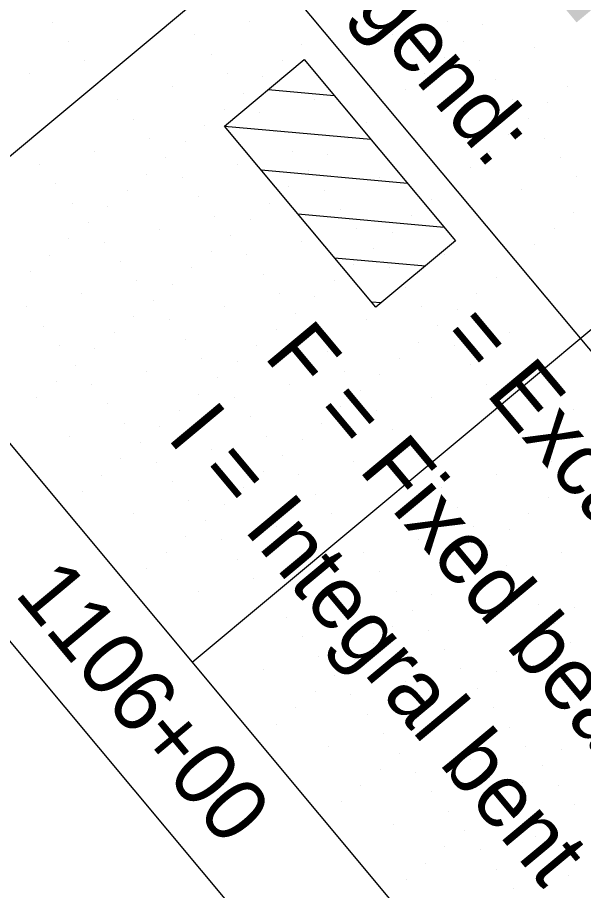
# Model space of a CAD drawing. Extents: x 2042995 to 2043795, y 305365 to 306249.
# Drawn here: x 2043226.41 to 2043248.8, y 305696.35 to 305730.9 of the extents above; entities that cross this region are included whole.
import ezdxf

# ---------------------------------------------------------------- set-up
doc = ezdxf.new("R2010")
doc.units = 0
for name, color, linetype in [('BR_AUTO DIMENSION', 7, 'Continuous'), ('BR_BORDER LINES', 7, 'Continuous'), ('BR_CONCRETE', 7, 'Continuous'), ('BR_GRID DOTS', 7, 'Continuous'), ('BR_GRID LINES', 7, 'Continuous'), ('BR_TABLE LINES', 7, 'Continuous'), ('BR_TEXT', 7, 'Continuous')]:
    doc.layers.add(name, color=color, linetype=linetype)

msp = doc.modelspace()

# ---------------------------------------------------------------- linework, layer by layer
at = {"layer": 'BR_BORDER LINES'}
for p, q in [((2043026.498, 305945.211), (2043458.121, 305428.416)), ((2043041.019, 305935.624), (2043355.122, 305559.54))]:
    msp.add_line(p, q, dxfattribs=at)
at = {"layer": 'BR_CONCRETE'}
msp.add_spline([(2043139.109, 306017.548), (2043148.199, 306007.16), (2043160.233, 305993.368), (2043172.245, 305979.557), (2043184.234, 305965.727), (2043196.201, 305951.879), (2043208.145, 305938.012), (2043220.067, 305924.126), (2043231.966, 305910.221), (2043243.843, 305896.297), (2043255.698, 305882.355), (2043267.529, 305868.394), (2043279.339, 305854.414), (2043291.126, 305840.415), (2043302.89, 305826.398), (2043314.632, 305812.361), (2043326.352, 305798.306), (2043338.049, 305784.233), (2043349.724, 305770.14), (2043361.376, 305756.029), (2043373.005, 305741.899), (2043384.613, 305727.75), (2043396.197, 305713.582), (2043407.76, 305699.396), (2043419.299, 305685.191), (2043430.817, 305670.967), (2043442.311, 305656.724), (2043453.784, 305642.463), (2043465.234, 305628.182), (2043476.661, 305613.883), (2043488.066, 305599.566), (2043499.448, 305585.229), (2043510.808, 305570.874), (2043522.146, 305556.5), (2043533.461, 305542.107), (2043544.753, 305527.695), (2043547.219, 305524.543)], degree=3, dxfattribs=at)
at = {"layer": 'BR_GRID DOTS'}
for p, q in [((2043227.793, 305730.714), (2043227.793, 305730.714)), ((2043235.604, 305730.722), (2043235.604, 305730.722)), ((2043238.421, 305730.469), (2043238.421, 305730.469)), ((2043243.414, 305730.731), (2043243.414, 305730.731)), ((2043244.822, 305730.604), (2043244.822, 305730.604)), ((2043233.428, 305730.208), (2043233.428, 305730.208)), ((2043241.238, 305730.216), (2043241.238, 305730.216)), ((2043228.434, 305729.946), (2043228.434, 305729.946)), ((2043237.653, 305729.828), (2043237.653, 305729.828)), ((2043244.055, 305729.963), (2043244.055, 305729.963)), ((2043234.069, 305729.44), (2043234.069, 305729.44)), ((2043246.872, 305729.71), (2043246.872, 305729.71)), ((2043229.076, 305729.179), (2043229.076, 305729.179)), ((2043236.886, 305729.187), (2043236.886, 305729.187)), ((2043243.287, 305729.322), (2043243.287, 305729.322)), ((2043244.696, 305729.196), (2043244.696, 305729.196)), ((2043226.899, 305728.664), (2043226.899, 305728.664)), ((2043234.71, 305728.673), (2043234.71, 305728.673)), ((2043236.118, 305728.546), (2043236.118, 305728.546)), ((2043242.52, 305728.681), (2043242.52, 305728.681)), ((2043245.337, 305728.428), (2043245.337, 305728.428)), ((2043232.534, 305728.158), (2043232.534, 305728.158)), ((2043241.752, 305728.04), (2043241.752, 305728.04)), ((2043248.154, 305728.175), (2043248.154, 305728.175)), ((2043235.351, 305727.905), (2043235.351, 305727.905)), ((2043230.358, 305727.644), (2043230.358, 305727.644)), ((2043238.168, 305727.652), (2043238.168, 305727.652)), ((2043240.985, 305727.399), (2043240.985, 305727.399)), ((2043245.978, 305727.661), (2043245.978, 305727.661)), ((2043247.387, 305727.534), (2043247.387, 305727.534)), ((2043234.583, 305727.264), (2043234.583, 305727.264)), ((2043235.992, 305727.138), (2043235.992, 305727.138)), ((2043243.802, 305727.146), (2043243.802, 305727.146)), ((2043230.999, 305726.876), (2043230.999, 305726.876)), ((2043240.217, 305726.758), (2043240.217, 305726.758)), ((2043246.619, 305726.893), (2043246.619, 305726.893)), ((2043233.816, 305726.623), (2043233.816, 305726.623)), ((2043236.633, 305726.37), (2043236.633, 305726.37)), ((2043231.64, 305726.109), (2043231.64, 305726.109)), ((2043233.048, 305725.982), (2043233.048, 305725.982)), ((2043239.45, 305726.117), (2043239.45, 305726.117)), ((2043245.852, 305726.252), (2043245.852, 305726.252)), ((2043247.26, 305726.126), (2043247.26, 305726.126)), ((2043237.274, 305725.603), (2043237.274, 305725.603)), ((2043245.084, 305725.611), (2043245.084, 305725.611)), ((2043229.464, 305725.594), (2043229.464, 305725.594)), ((2043232.281, 305725.341), (2043232.281, 305725.341)), ((2043238.682, 305725.476), (2043238.682, 305725.476)), ((2043247.901, 305725.358), (2043247.901, 305725.358)), ((2043227.287, 305725.08), (2043227.287, 305725.08)), ((2043235.098, 305725.088), (2043235.098, 305725.088)), ((2043244.317, 305724.97), (2043244.317, 305724.97)), ((2043231.513, 305724.7), (2043231.513, 305724.7)), ((2043232.922, 305724.574), (2043232.922, 305724.574)), ((2043237.915, 305724.835), (2043237.915, 305724.835)), ((2043240.732, 305724.582), (2043240.732, 305724.582)), ((2043248.542, 305724.591), (2043248.542, 305724.591)), ((2043227.929, 305724.312), (2043227.929, 305724.312)), ((2043243.549, 305724.329), (2043243.549, 305724.329)), ((2043230.746, 305724.059), (2043230.746, 305724.059)), ((2043237.147, 305724.194), (2043237.147, 305724.194)), ((2043238.556, 305724.068), (2043238.556, 305724.068)), ((2043246.366, 305724.076), (2043246.366, 305724.076)), ((2043228.57, 305723.545), (2043228.57, 305723.545)), ((2043233.563, 305723.806), (2043233.563, 305723.806)), ((2043236.38, 305723.553), (2043236.38, 305723.553)), ((2043242.781, 305723.688), (2043242.781, 305723.688)), ((2043229.978, 305723.418), (2043229.978, 305723.418)), ((2043239.197, 305723.3), (2043239.197, 305723.3)), ((2043248.416, 305723.182), (2043248.416, 305723.182)), ((2043234.204, 305723.039), (2043234.204, 305723.039)), ((2043235.612, 305722.912), (2043235.612, 305722.912)), ((2043242.014, 305723.047), (2043242.014, 305723.047)), ((2043229.211, 305722.777), (2043229.211, 305722.777)), ((2043232.028, 305722.524), (2043232.028, 305722.524)), ((2043239.838, 305722.533), (2043239.838, 305722.533)), ((2043247.648, 305722.541), (2043247.648, 305722.541)), ((2043234.845, 305722.271), (2043234.845, 305722.271)), ((2043241.246, 305722.406), (2043241.246, 305722.406)), ((2043228.443, 305722.136), (2043228.443, 305722.136)), ((2043229.852, 305722.009), (2043229.852, 305722.009)), ((2043237.662, 305722.018), (2043237.662, 305722.018)), ((2043246.881, 305721.9), (2043246.881, 305721.9)), ((2043227.676, 305721.495), (2043227.676, 305721.495)), ((2043234.077, 305721.63), (2043234.077, 305721.63)), ((2043235.486, 305721.503), (2043235.486, 305721.503)), ((2043240.479, 305721.765), (2043240.479, 305721.765)), ((2043243.296, 305721.512), (2043243.296, 305721.512)), ((2043230.493, 305721.242), (2043230.493, 305721.242)), ((2043239.711, 305721.124), (2043239.711, 305721.124)), ((2043246.113, 305721.259), (2043246.113, 305721.259)), ((2043226.908, 305720.854), (2043226.908, 305720.854)), ((2043233.31, 305720.989), (2043233.31, 305720.989)), ((2043241.12, 305720.998), (2043241.12, 305720.998)), ((2043231.134, 305720.474), (2043231.134, 305720.474)), ((2043236.127, 305720.736), (2043236.127, 305720.736)), ((2043238.944, 305720.483), (2043238.944, 305720.483)), ((2043245.346, 305720.618), (2043245.346, 305720.618)), ((2043232.542, 305720.348), (2043232.542, 305720.348)), ((2043241.761, 305720.23), (2043241.761, 305720.23)), ((2043228.958, 305719.96), (2043228.958, 305719.96)), ((2043236.768, 305719.968), (2043236.768, 305719.968)), ((2043238.176, 305719.842), (2043238.176, 305719.842)), ((2043244.578, 305719.977), (2043244.578, 305719.977)), ((2043226.782, 305719.445), (2043226.782, 305719.445)), ((2043231.775, 305719.707), (2043231.775, 305719.707)), ((2043234.592, 305719.454), (2043234.592, 305719.454)), ((2043242.402, 305719.462), (2043242.402, 305719.462)), ((2043231.007, 305719.066), (2043231.007, 305719.066)), ((2043237.409, 305719.201), (2043237.409, 305719.201)), ((2043243.811, 305719.336), (2043243.811, 305719.336)), ((2043232.416, 305718.939), (2043232.416, 305718.939)), ((2043240.226, 305718.948), (2043240.226, 305718.948)), ((2043243.043, 305718.695), (2043243.043, 305718.695)), ((2043227.423, 305718.678), (2043227.423, 305718.678)), ((2043230.24, 305718.425), (2043230.24, 305718.425)), ((2043236.641, 305718.56), (2043236.641, 305718.56)), ((2043238.05, 305718.433), (2043238.05, 305718.433)), ((2043245.86, 305718.442), (2043245.86, 305718.442)), ((2043233.057, 305718.172), (2043233.057, 305718.172)), ((2043242.276, 305718.054), (2043242.276, 305718.054)), ((2043228.064, 305717.91), (2043228.064, 305717.91)), ((2043229.472, 305717.784), (2043229.472, 305717.784)), ((2043235.874, 305717.919), (2043235.874, 305717.919)), ((2043238.691, 305717.666), (2043238.691, 305717.666)), ((2043243.684, 305717.927), (2043243.684, 305717.927)), ((2043233.698, 305717.404), (2043233.698, 305717.404)), ((2043241.508, 305717.413), (2043241.508, 305717.413)), ((2043228.705, 305717.143), (2043228.705, 305717.143)), ((2043235.106, 305717.278), (2043235.106, 305717.278)), ((2043244.325, 305717.16), (2043244.325, 305717.16)), ((2043231.522, 305716.89), (2043231.522, 305716.89)), ((2043234.339, 305716.637), (2043234.339, 305716.637)), ((2043239.332, 305716.898), (2043239.332, 305716.898)), ((2043240.74, 305716.772), (2043240.74, 305716.772)), ((2043227.937, 305716.502), (2043227.937, 305716.502)), ((2043229.346, 305716.375), (2043229.346, 305716.375)), ((2043237.156, 305716.384), (2043237.156, 305716.384)), ((2043244.966, 305716.392), (2043244.966, 305716.392)), ((2043233.571, 305715.996), (2043233.571, 305715.996)), ((2043239.973, 305716.131), (2043239.973, 305716.131)), ((2043227.17, 305715.861), (2043227.17, 305715.861)), ((2043229.987, 305715.608), (2043229.987, 305715.608)), ((2043234.98, 305715.869), (2043234.98, 305715.869)), ((2043242.79, 305715.878), (2043242.79, 305715.878)), ((2043232.804, 305715.355), (2043232.804, 305715.355)), ((2043239.205, 305715.49), (2043239.205, 305715.49)), ((2043240.614, 305715.363), (2043240.614, 305715.363)), ((2043248.424, 305715.372), (2043248.424, 305715.372)), ((2043235.621, 305715.102), (2043235.621, 305715.102)), ((2043230.628, 305714.84), (2043230.628, 305714.84)), ((2043232.036, 305714.714), (2043232.036, 305714.714)), ((2043238.438, 305714.849), (2043238.438, 305714.849)), ((2043241.255, 305714.596), (2043241.255, 305714.596)), ((2043246.248, 305714.857), (2043246.248, 305714.857)), ((2043228.452, 305714.326), (2043228.452, 305714.326)), ((2043236.262, 305714.334), (2043236.262, 305714.334)), ((2043237.67, 305714.208), (2043237.67, 305714.208)), ((2043231.269, 305714.073), (2043231.269, 305714.073)), ((2043246.889, 305714.09), (2043246.889, 305714.09)), ((2043234.086, 305713.82), (2043234.086, 305713.82)), ((2043236.903, 305713.567), (2043236.903, 305713.567)), ((2043241.896, 305713.828), (2043241.896, 305713.828)), ((2043230.501, 305713.432), (2043230.501, 305713.432)), ((2043231.91, 305713.305), (2043231.91, 305713.305)), ((2043239.72, 305713.314), (2043239.72, 305713.314)), ((2043247.53, 305713.322), (2043247.53, 305713.322)), ((2043236.135, 305712.926), (2043236.135, 305712.926)), ((2043229.734, 305712.791), (2043229.734, 305712.791)), ((2043232.551, 305712.538), (2043232.551, 305712.538)), ((2043237.544, 305712.799), (2043237.544, 305712.799)), ((2043245.354, 305712.808), (2043245.354, 305712.808)), ((2043248.171, 305712.555), (2043248.171, 305712.555)), ((2043228.966, 305712.15), (2043228.966, 305712.15)), ((2043235.368, 305712.285), (2043235.368, 305712.285)), ((2043243.178, 305712.293), (2043243.178, 305712.293)), ((2043238.185, 305712.032), (2043238.185, 305712.032)), ((2043247.404, 305711.914), (2043247.404, 305711.914)), ((2043233.192, 305711.77), (2043233.192, 305711.77)), ((2043234.6, 305711.644), (2043234.6, 305711.644)), ((2043243.819, 305711.526), (2043243.819, 305711.526)), ((2043231.016, 305711.256), (2043231.016, 305711.256)), ((2043238.826, 305711.264), (2043238.826, 305711.264)), ((2043246.636, 305711.273), (2043246.636, 305711.273)), ((2043233.833, 305711.003), (2043233.833, 305711.003)), ((2043236.65, 305710.75), (2043236.65, 305710.75)), ((2043244.46, 305710.758), (2043244.46, 305710.758)), ((2043245.869, 305710.632), (2043245.869, 305710.632)), ((2043233.065, 305710.362), (2043233.065, 305710.362)), ((2043234.474, 305710.235), (2043234.474, 305710.235)), ((2043242.284, 305710.244), (2043242.284, 305710.244)), ((2043232.298, 305709.721), (2043232.298, 305709.721)), ((2043240.108, 305709.729), (2043240.108, 305709.729)), ((2043245.101, 305709.991), (2043245.101, 305709.991)), ((2043247.918, 305709.738), (2043247.918, 305709.738)), ((2043235.115, 305709.468), (2043235.115, 305709.468)), ((2043231.53, 305709.08), (2043231.53, 305709.08)), ((2043244.334, 305709.35), (2043244.334, 305709.35)), ((2043245.742, 305709.223), (2043245.742, 305709.223)), ((2043235.756, 305708.7), (2043235.756, 305708.7)), ((2043240.749, 305708.962), (2043240.749, 305708.962)), ((2043243.566, 305708.709), (2043243.566, 305708.709)), ((2043246.383, 305708.456), (2043246.383, 305708.456)), ((2043233.58, 305708.186), (2043233.58, 305708.186)), ((2043241.39, 305708.194), (2043241.39, 305708.194)), ((2043242.799, 305708.068), (2043242.799, 305708.068)), ((2043239.214, 305707.68), (2043239.214, 305707.68)), ((2043247.024, 305707.688), (2043247.024, 305707.688)), ((2043242.031, 305707.427), (2043242.031, 305707.427)), ((2043248.433, 305707.562), (2043248.433, 305707.562)), ((2043237.038, 305707.165), (2043237.038, 305707.165)), ((2043244.848, 305707.174), (2043244.848, 305707.174)), ((2043241.264, 305706.786), (2043241.264, 305706.786)), ((2043242.672, 305706.659), (2043242.672, 305706.659)), ((2043247.665, 305706.921), (2043247.665, 305706.921)), ((2043237.679, 305706.398), (2043237.679, 305706.398)), ((2043246.898, 305706.28), (2043246.898, 305706.28)), ((2043240.496, 305706.145), (2043240.496, 305706.145)), ((2043248.306, 305706.153), (2043248.306, 305706.153)), ((2043238.32, 305705.63), (2043238.32, 305705.63)), ((2043243.313, 305705.892), (2043243.313, 305705.892)), ((2043246.13, 305705.639), (2043246.13, 305705.639)), ((2043239.729, 305705.504), (2043239.729, 305705.504)), ((2043236.144, 305705.115), (2043236.144, 305705.115)), ((2043243.954, 305705.124), (2043243.954, 305705.124)), ((2043245.363, 305704.998), (2043245.363, 305704.998)), ((2043238.961, 305704.863), (2043238.961, 305704.863)), ((2043241.778, 305704.61), (2043241.778, 305704.61)), ((2043238.193, 305704.221), (2043238.193, 305704.221)), ((2043244.595, 305704.357), (2043244.595, 305704.357)), ((2043239.602, 305704.095), (2043239.602, 305704.095)), ((2043247.412, 305704.104), (2043247.412, 305704.104)), ((2043237.426, 305703.58), (2043237.426, 305703.58)), ((2043243.828, 305703.716), (2043243.828, 305703.716)), ((2043245.236, 305703.589), (2043245.236, 305703.589)), ((2043240.243, 305703.327), (2043240.243, 305703.327)), ((2043236.658, 305702.939), (2043236.658, 305702.939)), ((2043243.06, 305703.074), (2043243.06, 305703.074)), ((2043245.877, 305702.821), (2043245.877, 305702.821)), ((2043240.884, 305702.56), (2043240.884, 305702.56)), ((2043248.694, 305702.569), (2043248.694, 305702.569)), ((2043242.293, 305702.433), (2043242.293, 305702.433)), ((2043238.708, 305702.045), (2043238.708, 305702.045)), ((2043241.525, 305701.792), (2043241.525, 305701.792)), ((2043246.518, 305702.054), (2043246.518, 305702.054)), ((2043247.927, 305701.927), (2043247.927, 305701.927)), ((2043244.342, 305701.539), (2043244.342, 305701.539)), ((2043240.758, 305701.151), (2043240.758, 305701.151)), ((2043247.159, 305701.286), (2043247.159, 305701.286)), ((2043242.166, 305701.025), (2043242.166, 305701.025)), ((2043239.99, 305700.51), (2043239.99, 305700.51)), ((2043246.392, 305700.645), (2043246.392, 305700.645)), ((2043247.8, 305700.519), (2043247.8, 305700.519)), ((2043242.807, 305700.257), (2043242.807, 305700.257)), ((2043239.223, 305699.869), (2043239.223, 305699.869)), ((2043245.624, 305700.004), (2043245.624, 305700.004)), ((2043248.441, 305699.751), (2043248.441, 305699.751)), ((2043243.448, 305699.49), (2043243.448, 305699.49)), ((2043244.857, 305699.363), (2043244.857, 305699.363)), ((2043241.272, 305698.975), (2043241.272, 305698.975)), ((2043244.089, 305698.722), (2043244.089, 305698.722)), ((2043246.906, 305698.469), (2043246.906, 305698.469)), ((2043243.322, 305698.081), (2043243.322, 305698.081)), ((2043244.73, 305697.955), (2043244.73, 305697.955)), ((2043242.554, 305697.44), (2043242.554, 305697.44)), ((2043245.371, 305697.187), (2043245.371, 305697.187)), ((2043248.188, 305696.934), (2043248.188, 305696.934)), ((2043241.787, 305696.799), (2043241.787, 305696.799)), ((2043246.012, 305696.42), (2043246.012, 305696.42))]:
    msp.add_line(p, q, dxfattribs=at)
at = {"layer": 'BR_GRID LINES'}
for p, q in [((2043133.293, 305856.342), (2043340.985, 305607.666)), ((2043374.01, 305848.924), (2043220.506, 305720.719)), ((2043386.831, 305833.574), (2043233.327, 305705.368))]:
    msp.add_line(p, q, dxfattribs=at)
at = {"layer": 'BR_TABLE LINES'}
for p, q in [((2043236.334, 305728.048), (2043238.939, 305727.814)), ((2043234.597, 305726.598), (2043240.389, 305726.077)), ((2043236.048, 305724.861), (2043241.84, 305724.341)), ((2043237.498, 305723.124), (2043243.29, 305722.604)), ((2043238.949, 305721.387), (2043242.545, 305721.064)), ((2043240.399, 305719.651), (2043240.808, 305719.614))]:
    msp.add_line(p, q, dxfattribs=at)
msp.add_lwpolyline([(2043237.753, 305729.233), (2043243.741, 305722.064), (2043240.585, 305719.428), (2043234.597, 305726.598)], close=True, dxfattribs=at)

# ---------------------------------------------------------------- texts
at = {"layer": 'BR_AUTO DIMENSION'}
for s, p in [('Legend:', (2043237.356, 305734.112)), ('= Excavate hatched area (See Road Plans)', (2043243.051, 305718.224)), ('F = Fixed bearing', (2043236.118, 305717.487)), ('I = Integral bent', (2043232.28, 305714.282))]:
    msp.add_text(s, height=2.5, rotation=309.8684, dxfattribs=at).set_placement(p)
at = {"layer": 'BR_TEXT'}
for s, height, p in [('SECTION ALONG L US 17A  US 21', 8.12508, (2043221.449, 305763.122)), ('1106+00', 2.5, (2043226.258, 305708.082))]:
    msp.add_text(s, height=height, rotation=309.8684, dxfattribs=at).set_placement(p)

doc.saveas('drawing.dxf')
